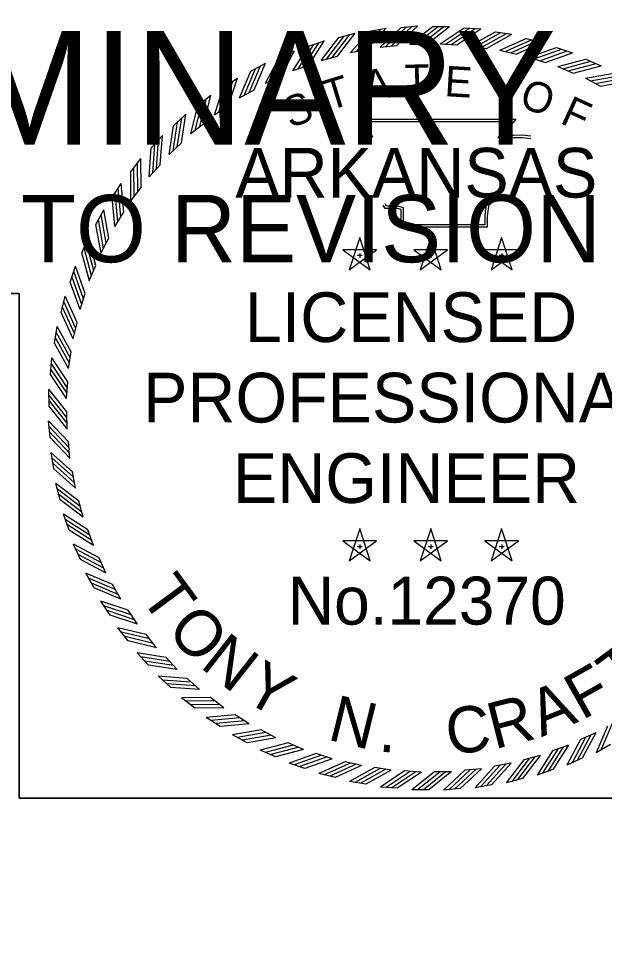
# Model space of a CAD drawing. Extents: x 0 to 1228740, y 0 to 152440.
# Drawn here: x 30.665 to 32.645, y 17.279 to 20.411 of the extents above; entities that cross this region are included whole.
import ezdxf

# ---------------------------------------------------------------- set-up
doc = ezdxf.new("R2010")
doc.units = 0
for name, color, linetype in [('R_Draft', 7, 'Continuous'), ('R_No Plot', 7, 'Continuous'), ('STAMP_TNC', 7, 'Continuous')]:
    doc.layers.add(name, color=color, linetype=linetype)

msp = doc.modelspace()

# ---------------------------------------------------------------- linework, layer by layer
at = {"layer": 'R_No Plot'}
msp.add_lwpolyline([(27.1591, 21.4232), (1.516, 21.4232), (1.516, 10.8708), (33.4231, 10.8708), (33.4231, 17.7768), (30.6665, 17.7768), (30.6665, 19.4815), (28.8871, 19.4815), (28.8871, 20.4352), (27.1591, 20.4352)], close=True, dxfattribs=at)
for points in [[(33.4231, 17.7768), (33.4231, 0.5768), (1.516, 0.5768), (1.516, 21.4232), (27.1591, 21.4232), (27.1591, 20.4352), (28.8871, 20.4352), (28.8871, 19.4815), (30.6665, 19.4815)], [(30.6665, 19.4815), (30.6665, 17.7768), (33.4231, 17.7768)]]:
    msp.add_lwpolyline(points, dxfattribs=at)
at = {"layer": 'STAMP_TNC'}
for p, q in [((31.7473, 20.3469), (31.802, 20.3613)), ((31.8517, 20.3683), (31.9074, 20.3781)), ((31.9576, 20.3809), (32.0139, 20.3861)), ((32.0647, 20.3841), (32.1212, 20.3841)), ((32.1706, 20.3798), (32.227, 20.3757)), ((32.2763, 20.3661), (32.3321, 20.3573)), ((31.645, 20.317), (31.6983, 20.3359)), ((32.0892, 20.3255), (32.1457, 20.3213)), ((32.3805, 20.3437), (32.4354, 20.3303)), ((31.5455, 20.2788), (31.597, 20.302)), ((31.7862, 20.2956), (31.842, 20.3055)), ((31.8862, 20.3139), (31.9427, 20.3191)), ((31.9875, 20.3239), (32.0442, 20.3239)), ((32.1907, 20.3187), (32.2467, 20.3099)), ((32.2913, 20.3035), (32.3464, 20.2901)), ((32.4825, 20.3128), (32.5362, 20.2949)), ((31.688, 20.2691), (31.7428, 20.2835)), ((32.3903, 20.2801), (32.4441, 20.2622)), ((32.5816, 20.2735), (32.6336, 20.2513)), ((31.4495, 20.2325), (31.4989, 20.2598)), ((31.5923, 20.2346), (31.6457, 20.2535)), ((32.487, 20.2485), (32.5391, 20.2262)), ((31.3576, 20.1784), (31.4047, 20.2097)), ((31.4998, 20.1923), (31.5515, 20.2155)), ((32.5808, 20.2091), (32.6309, 20.1826)), ((31.4111, 20.1425), (31.4607, 20.1699)), ((31.2705, 20.1169), (31.3148, 20.152)), ((31.3268, 20.0855), (31.3739, 20.1169)), ((31.1888, 20.0484), (31.2301, 20.0871)), ((31.2475, 20.0218), (31.2919, 20.057)), ((31.1131, 19.9734), (31.151, 20.0154)), ((31.1737, 19.9517), (31.2151, 19.9905)), ((31.0438, 19.8924), (31.0781, 19.9374)), ((31.106, 19.8758), (31.144, 19.9179)), ((30.9814, 19.806), (31.0119, 19.8536)), ((31.0448, 19.7946), (31.0792, 19.8396)), ((30.9264, 19.7147), (30.9528, 19.7647)), ((30.9905, 19.7085), (31.021, 19.7563)), ((30.8791, 19.6192), (30.9013, 19.6712)), ((30.9434, 19.6183), (30.97, 19.6684)), ((31.8175, 19.6706), (31.7822, 19.562)), ((31.8528, 19.5621), (31.8176, 19.6707)), ((32.0574, 19.6706), (32.022, 19.562)), ((32.0927, 19.5621), (32.0575, 19.6707)), ((32.2973, 19.6706), (32.2619, 19.562)), ((32.3325, 19.5621), (32.2973, 19.6707)), ((31.8746, 19.6291), (31.7604, 19.6293)), ((31.7605, 19.6291), (31.8528, 19.562)), ((31.7823, 19.5621), (31.8747, 19.6291)), ((31.8094, 19.6109), (31.8264, 19.6109)), ((31.8176, 19.617), (31.8176, 19.6027)), ((32.1144, 19.6291), (32.0003, 19.6293)), ((32.0004, 19.6291), (32.0927, 19.562)), ((32.0222, 19.5621), (32.1146, 19.6291)), ((32.0493, 19.6109), (32.0662, 19.6109)), ((32.0575, 19.617), (32.0575, 19.6027)), ((32.3543, 19.6291), (32.2401, 19.6293)), ((32.2402, 19.6291), (32.3325, 19.562)), ((32.262, 19.5621), (32.3544, 19.6291)), ((32.2891, 19.6109), (32.3061, 19.6109)), ((32.2974, 19.617), (32.2974, 19.6027)), ((30.8398, 19.5201), (30.8577, 19.5737)), ((30.904, 19.5245), (30.9263, 19.5767)), ((30.8725, 19.4278), (30.8904, 19.4816)), ((30.8089, 19.418), (30.8222, 19.473)), ((30.7865, 19.3138), (30.7952, 19.3697)), ((30.8491, 19.3288), (30.8625, 19.3839)), ((30.7727, 19.2081), (30.7769, 19.2645)), ((30.8339, 19.2282), (30.8427, 19.2842)), ((30.8271, 19.1267), (30.8312, 19.1833)), ((30.7678, 19.1016), (30.7673, 19.1582)), ((30.8287, 19.025), (30.8281, 19.0817)), ((30.7716, 18.9951), (30.7665, 19.0514)), ((30.8386, 18.9238), (30.8334, 18.9802)), ((30.7843, 18.8893), (30.7745, 18.945)), ((30.857, 18.8237), (30.8471, 18.8795)), ((30.8056, 18.7848), (30.7912, 18.8395)), ((30.8835, 18.7255), (30.869, 18.7803)), ((30.8355, 18.6825), (30.8167, 18.7358)), ((30.918, 18.6298), (30.8991, 18.6833)), ((31.8175, 18.6871), (31.7822, 18.5785)), ((31.8528, 18.5786), (31.8176, 18.6872)), ((32.0574, 18.6871), (32.022, 18.5785)), ((32.0927, 18.5786), (32.0575, 18.6872)), ((32.2973, 18.6871), (32.2619, 18.5785)), ((32.3325, 18.5786), (32.2973, 18.6872)), ((30.8738, 18.583), (30.8506, 18.6346)), ((31.8746, 18.6456), (31.7604, 18.6458)), ((31.7605, 18.6456), (31.8528, 18.5785)), ((31.7823, 18.5786), (31.8747, 18.6456)), ((31.8176, 18.6335), (31.8176, 18.6192)), ((32.1144, 18.6456), (32.0003, 18.6458)), ((32.0004, 18.6456), (32.0927, 18.5785)), ((32.0222, 18.5786), (32.1146, 18.6456)), ((32.0575, 18.6335), (32.0575, 18.6192)), ((32.3543, 18.6456), (32.2401, 18.6458)), ((32.2402, 18.6456), (32.3325, 18.5785)), ((32.262, 18.5786), (32.3544, 18.6456)), ((32.2974, 18.6335), (32.2974, 18.6192)), ((31.8094, 18.6274), (31.8264, 18.6274)), ((32.0493, 18.6274), (32.0662, 18.6274)), ((32.2891, 18.6274), (32.3061, 18.6274)), ((30.9603, 18.5373), (30.9371, 18.589)), ((30.9201, 18.487), (30.8927, 18.5365)), ((31.0101, 18.4486), (30.9827, 18.4982)), ((30.9742, 18.3952), (30.9428, 18.4422)), ((31.0671, 18.3643), (31.0356, 18.4115)), ((31.0357, 18.3081), (31.0005, 18.3524)), ((31.1308, 18.285), (31.0956, 18.3294)), ((31.1042, 18.2264), (31.0655, 18.2676)), ((31.2009, 18.2113), (31.1621, 18.2526)), ((31.1792, 18.1506), (31.1372, 18.1885)), ((31.2768, 18.1435), (31.2347, 18.1815)), ((31.2601, 18.0813), (31.2152, 18.1156)), ((31.358, 18.0823), (31.313, 18.1167)), ((31.3466, 18.0189), (31.299, 18.0494)), ((31.444, 18.028), (31.3963, 18.0586)), ((31.5342, 17.981), (31.4841, 18.0075)), ((31.4379, 17.9639), (31.3879, 17.9904)), ((32.6153, 17.9978), (32.5636, 17.9746)), ((31.628, 17.9416), (31.5759, 17.9639)), ((32.5228, 17.9555), (32.4693, 17.9366)), ((32.6656, 17.9576), (32.6161, 17.9303)), ((31.5334, 17.9166), (31.4814, 17.9388)), ((31.7247, 17.9101), (31.671, 17.928)), ((32.4271, 17.921), (32.3722, 17.9066)), ((31.6325, 17.8773), (31.5789, 17.8952)), ((31.8237, 17.8866), (31.7687, 17.9)), ((32.3289, 17.8945), (32.273, 17.8847)), ((32.5696, 17.9113), (32.518, 17.8881)), ((31.7345, 17.8464), (31.6796, 17.8598)), ((31.9243, 17.8714), (31.8683, 17.8803)), ((32.0258, 17.8646), (31.9693, 17.8688)), ((32.1275, 17.8662), (32.0709, 17.8657)), ((32.2288, 17.8762), (32.1723, 17.871)), ((32.4701, 17.8731), (32.4167, 17.8542)), ((31.8387, 17.824), (31.7829, 17.8328)), ((32.2633, 17.8218), (32.2076, 17.812)), ((32.3677, 17.8432), (32.3131, 17.8288)), ((31.9444, 17.8103), (31.8881, 17.8144)), ((32.0509, 17.8053), (31.9944, 17.8048)), ((32.1575, 17.8092), (32.1011, 17.804))]:
    msp.add_line(p, q, dxfattribs=at)
for points in [[(31.7244, 20.2789), (31.7837, 20.3568)], [(31.7427, 20.2836), (31.802, 20.3614)], [(31.7861, 20.2956), (31.8517, 20.3682)], [(31.8041, 20.2986), (31.8696, 20.3712)], [(31.8233, 20.3024), (31.8889, 20.3751)], [(31.8419, 20.3055), (31.9075, 20.3782)], [(31.8862, 20.3139), (31.9575, 20.3809)], [(31.9043, 20.3154), (31.9756, 20.3824)], [(31.9238, 20.3176), (31.9952, 20.3846)], [(31.9426, 20.3192), (32.0139, 20.3862)], [(31.9874, 20.3239), (32.0646, 20.384)], [(32.0056, 20.3237), (32.0828, 20.3839)], [(32.0253, 20.3241), (32.1024, 20.3843)], [(32.0441, 20.3239), (32.1213, 20.3841)], [(32.0891, 20.3254), (32.1705, 20.3798)], [(32.1073, 20.3239), (32.1886, 20.3783)], [(32.1269, 20.3229), (32.2083, 20.3773)], [(32.1457, 20.3214), (32.227, 20.3757)], [(32.1906, 20.3186), (32.2762, 20.3661)], [(32.2086, 20.3156), (32.2942, 20.3631)], [(32.228, 20.313), (32.3136, 20.3605)], [(32.2466, 20.3099), (32.3322, 20.3574)], [(31.6278, 20.2474), (31.6805, 20.3298)], [(31.6456, 20.2535), (31.6983, 20.336)], [(31.6879, 20.269), (31.7472, 20.3469)], [(31.7056, 20.2735), (31.7649, 20.3513)], [(32.2912, 20.3035), (32.3804, 20.3437)], [(32.3089, 20.299), (32.3981, 20.3392)], [(32.328, 20.2948), (32.4172, 20.335)], [(32.3463, 20.2901), (32.4355, 20.3304)], [(31.5341, 20.208), (31.5798, 20.2945)], [(31.5514, 20.2155), (31.5971, 20.3021)], [(31.5922, 20.2345), (31.6449, 20.317)], [(31.6094, 20.2404), (31.6621, 20.3229)], [(32.3902, 20.28), (32.4824, 20.3127)], [(32.4074, 20.2741), (32.4996, 20.3068)], [(32.4262, 20.2683), (32.5184, 20.301)], [(32.444, 20.2622), (32.5362, 20.2949)], [(31.4997, 20.1922), (31.5454, 20.2787)], [(31.5164, 20.1995), (31.5621, 20.286)], [(32.4869, 20.2485), (32.5815, 20.2735)], [(32.5036, 20.2412), (32.5982, 20.2662)], [(31.411, 20.1424), (31.4494, 20.2324)], [(31.427, 20.1511), (31.4654, 20.2411)], [(31.444, 20.1609), (31.4824, 20.2509)], [(31.4606, 20.1699), (31.499, 20.2599)], [(32.5218, 20.2339), (32.6164, 20.2589)], [(32.5391, 20.2263), (32.6337, 20.2513)], [(31.3581, 20.1066), (31.3889, 20.1995)], [(31.3739, 20.1169), (31.4047, 20.2098)], [(32.5807, 20.2091), (32.677, 20.2262)], [(32.5967, 20.2005), (32.6931, 20.2175)], [(32.6143, 20.1916), (32.7106, 20.2087)], [(32.6308, 20.1827), (32.7272, 20.1998)], [(31.3267, 20.0854), (31.3576, 20.1783)], [(31.342, 20.0954), (31.3728, 20.1882)], [(31.2769, 20.0454), (31.3, 20.1405)], [(31.2918, 20.057), (31.3149, 20.1521)], [(31.2475, 20.0217), (31.2705, 20.1168)], [(31.2618, 20.0329), (31.2849, 20.128)], [(31.2011, 19.9777), (31.2162, 20.0744)], [(31.215, 19.9905), (31.2301, 20.0871)], [(31.1737, 19.9516), (31.1888, 20.0483)], [(31.1871, 19.964), (31.2022, 20.0606)], [(31.854, 20.0056), (31.8238, 20.0709), (32.3454, 20.0712), (32.3018, 20.0164), (32.3372, 20.0169), (32.3668, 20.0173), (32.3964, 20.0141)], [(31.8615, 20.0091), (31.8367, 20.0626), (32.3282, 20.0629), (32.2845, 20.0079), (32.3373, 20.0086), (32.3664, 20.009), (32.3955, 20.0058)], [(31.1439, 19.9178), (31.151, 20.0154)], [(31.1183, 19.8891), (31.1254, 19.9867)], [(31.1312, 19.904), (31.1382, 20.0016)], [(31.106, 19.8757), (31.1131, 19.9733)], [(31.0675, 19.8247), (31.0665, 19.9226)], [(31.0791, 19.8396), (31.0781, 19.9374)], [(31.0448, 19.7945), (31.0438, 19.8923)], [(31.0559, 19.8088), (31.0549, 19.9067)], [(31.0106, 19.7405), (31.0016, 19.8379)], [(31.021, 19.7562), (31.0119, 19.8537)], [(30.9905, 19.7085), (30.9814, 19.8059)], [(31.0004, 19.7237), (30.9913, 19.8211)], [(32.258, 19.7934), (32.247, 19.7845), (32.2432, 19.7705), (32.2401, 19.7424), (32.2401, 19.7142), (31.9655, 19.7142), (31.9655, 19.7546), (31.9655, 19.7715), (31.9467, 19.7772), (31.9085, 19.7772), (31.9036, 19.7847)], [(30.9699, 19.6684), (30.9528, 19.7647)], [(32.2632, 19.787), (32.2543, 19.7798), (32.2513, 19.769), (32.2484, 19.742), (32.2484, 19.7059), (31.9572, 19.7059), (31.9572, 19.7546), (31.9572, 19.7654), (31.9454, 19.769), (31.904, 19.769), (31.8967, 19.7802)], [(30.9521, 19.6343), (30.935, 19.7306)], [(30.9609, 19.6518), (30.9438, 19.7482)], [(30.9435, 19.6183), (30.9264, 19.7146)], [(30.9263, 19.5766), (30.9013, 19.6712)], [(30.9114, 19.5411), (30.8864, 19.6357)], [(30.9187, 19.5594), (30.8937, 19.654)], [(30.9041, 19.5245), (30.8791, 19.6191)], [(30.8904, 19.4816), (30.8576, 19.5738)], [(30.8842, 19.4637), (30.8515, 19.556)], [(30.8725, 19.4277), (30.8398, 19.52)], [(30.8784, 19.445), (30.8457, 19.5372)], [(30.8578, 19.3656), (30.8176, 19.4548)], [(30.8624, 19.3839), (30.8222, 19.4731)], [(30.8491, 19.3288), (30.8089, 19.418)], [(30.8536, 19.3464), (30.8134, 19.4356)], [(30.8427, 19.2842), (30.7952, 19.3698)], [(30.8369, 19.2461), (30.7895, 19.3317)], [(30.8396, 19.2656), (30.7921, 19.3512)], [(30.8339, 19.2282), (30.7865, 19.3137)], [(30.8312, 19.1832), (30.7768, 19.2646)], [(30.8296, 19.1644), (30.7753, 19.2458)], [(30.8271, 19.1267), (30.7728, 19.208)], [(30.8286, 19.1448), (30.7743, 19.2262)], [(30.8281, 19.0816), (30.7672, 19.1582)], [(30.8281, 19.0628), (30.7672, 19.1394)], [(30.8287, 19.0432), (30.7678, 19.1198)], [(30.8287, 19.025), (30.7678, 19.1016)], [(30.8334, 18.9802), (30.7664, 19.0515)], [(30.835, 18.9614), (30.768, 19.0327)], [(30.8372, 18.9419), (30.7702, 19.0132)], [(30.8387, 18.9237), (30.7717, 18.995)], [(30.8471, 18.8795), (30.7744, 18.945)], [(30.8502, 18.8609), (30.7775, 18.9264)], [(30.854, 18.8416), (30.7814, 18.9072)], [(30.857, 18.8237), (30.7844, 18.8892)], [(30.869, 18.7802), (30.7912, 18.8396)], [(30.8736, 18.762), (30.7958, 18.8213)], [(30.8791, 18.7431), (30.8012, 18.8024)], [(30.8835, 18.7255), (30.8057, 18.7848)], [(30.8991, 18.6832), (30.8166, 18.7359)], [(30.9052, 18.6654), (30.8227, 18.718)], [(30.9121, 18.647), (30.8297, 18.6997)], [(30.9181, 18.6298), (30.8356, 18.6825)], [(30.937, 18.5889), (30.8505, 18.6346)], [(30.9446, 18.5717), (30.8581, 18.6174)], [(30.9531, 18.5539), (30.8665, 18.5996)], [(30.9604, 18.5373), (30.8738, 18.583)], [(30.9827, 18.4981), (30.8927, 18.5365)], [(30.9916, 18.4816), (30.9016, 18.5199)], [(31.0015, 18.4646), (30.9115, 18.503)], [(31.0102, 18.4486), (30.9202, 18.487)], [(31.0356, 18.4114), (30.9428, 18.4422)], [(31.0459, 18.3956), (30.9531, 18.4265)], [(31.0572, 18.3795), (30.9643, 18.4104)], [(31.0671, 18.3643), (30.9743, 18.3951)], [(31.0956, 18.3294), (31.0005, 18.3524)], [(31.1071, 18.3145), (31.0121, 18.3375)], [(31.1197, 18.2994), (31.0246, 18.3224)], [(31.1309, 18.285), (31.0358, 18.3081)], [(31.1621, 18.2525), (31.0654, 18.2677)], [(31.1749, 18.2387), (31.0782, 18.2538)], [(31.1886, 18.2246), (31.0919, 18.2398)], [(31.2009, 18.2112), (31.1043, 18.2264)], [(31.2347, 18.1815), (31.1371, 18.1886)], [(31.2486, 18.1687), (31.151, 18.1758)], [(31.2635, 18.1559), (31.1659, 18.1629)], [(31.2768, 18.1435), (31.1793, 18.1506)], [(31.313, 18.1166), (31.2151, 18.1156)], [(31.3279, 18.1051), (31.23, 18.1041)], [(31.3437, 18.0935), (31.2459, 18.0925)], [(31.3581, 18.0823), (31.2602, 18.0813)], [(31.3963, 18.0585), (31.2989, 18.0494)], [(31.4121, 18.0482), (31.3147, 18.0391)], [(31.4289, 18.038), (31.3314, 18.0289)], [(31.4441, 18.028), (31.3467, 18.0189)], [(31.4842, 18.0074), (31.3878, 17.9904)], [(32.6544, 18.0202), (32.6161, 17.9302)], [(32.671, 18.0292), (32.6326, 17.9392)], [(31.5007, 17.9985), (31.4044, 17.9814)], [(31.5183, 17.9897), (31.422, 17.9726)], [(31.5343, 17.981), (31.438, 17.9639)], [(32.5809, 17.9822), (32.5352, 17.8956)], [(32.5986, 17.9906), (32.5529, 17.9041)], [(32.6153, 17.9979), (32.5696, 17.9114)], [(31.576, 17.9638), (31.4813, 17.9388)], [(31.5932, 17.9562), (31.4986, 17.9313)], [(31.6114, 17.9489), (31.5168, 17.9239)], [(32.5056, 17.9497), (32.4529, 17.8672)], [(32.5228, 17.9556), (32.4701, 17.8731)], [(32.5636, 17.9746), (32.518, 17.8881)], [(31.6281, 17.9416), (31.5335, 17.9166)], [(31.671, 17.9279), (31.5788, 17.8952)], [(31.6888, 17.9218), (31.5966, 17.8891)], [(31.7076, 17.916), (31.6154, 17.8833)], [(32.4095, 17.9166), (32.3502, 17.8388)], [(32.4271, 17.9211), (32.3678, 17.8433)], [(32.4694, 17.9366), (32.4167, 17.8542)], [(32.4872, 17.9427), (32.4345, 17.8603)], [(31.7248, 17.9101), (31.6326, 17.8774)], [(31.7687, 17.9), (31.6795, 17.8598)], [(31.787, 17.8954), (31.6978, 17.8551)], [(31.8062, 17.8911), (31.717, 17.8509)], [(31.8238, 17.8867), (31.7346, 17.8464)], [(32.2731, 17.8846), (32.2076, 17.812)], [(32.2917, 17.8877), (32.2262, 17.8151)], [(32.311, 17.8916), (32.2454, 17.8189)], [(32.3289, 17.8946), (32.2634, 17.8219)], [(32.3723, 17.9066), (32.313, 17.8287)], [(32.3906, 17.9112), (32.3313, 17.8334)], [(31.8684, 17.8802), (31.7828, 17.8328)], [(31.887, 17.8771), (31.8014, 17.8297)], [(31.9064, 17.8745), (31.8209, 17.827)], [(31.9244, 17.8715), (31.8388, 17.824)], [(31.9694, 17.8687), (31.888, 17.8144)], [(31.9881, 17.8672), (31.9068, 17.8128)], [(32.0078, 17.8662), (31.9264, 17.8118)], [(32.0259, 17.8647), (31.9445, 17.8103)], [(32.0709, 17.8657), (31.9943, 17.8048)], [(32.0898, 17.8657), (32.0132, 17.8048)], [(32.1094, 17.8663), (32.0328, 17.8054)], [(32.1276, 17.8663), (32.051, 17.8054)], [(32.1724, 17.871), (32.1011, 17.804)], [(32.1912, 17.8725), (32.1199, 17.8055)], [(32.2107, 17.8747), (32.1394, 17.8077)], [(32.2288, 17.8763), (32.1575, 17.8093)]]:
    msp.add_lwpolyline(points, dxfattribs=at)

# ---------------------------------------------------------------- texts
at = {"layer": 'R_Draft'}
for s, height, p in [('PRELIMINARY', 0.383593, (29.0049, 19.9851)), ('SUBJECT TO REVISION', 0.227428, (29.2031, 19.5873))]:
    msp.add_text(s, height=height, rotation=0, dxfattribs=at).set_placement(p)
at = {"layer": 'STAMP_TNC'}
for s, height, rotation, p in [('A', 0.1029, 8.6788, (31.8381, 20.1312)), ('T', 0.1029, 1.4789, (31.9709, 20.1516)), ('E', 0.1029, 356.672, (32.1026, 20.1485)), ('T', 0.1029, 16.9015, (31.7131, 20.0985)), ('O', 0.1029, 341.2218, (32.3524, 20.1132)), ('S', 0.1029, 19.7726, (31.5823, 20.0398)), ('F', 0.1029, 335.3628, (32.491, 20.059)), ('T', 0.1562, 306.5026, (31.0716, 18.4581)), ('O', 0.1562, 313.7811, (31.1603, 18.3383)), ('N', 0.1562, 321.7876, (31.2744, 18.2207)), ('T', 0.1562, 36.7567, (32.6989, 18.112)), ('Y', 0.1562, 330.5218, (31.4163, 18.1119)), ('F', 0.1562, 29.4782, (32.5692, 18.0387)), ('A', 0.1562, 22.1996, (32.4312, 17.9824)), ('N', 0.1562, 346.1707, (31.7053, 17.9754)), ('R', 0.1562, 14.1932, (32.2726, 17.9412)), ('C', 0.1562, 6.5507, (32.1172, 17.9228)), ('.', 0.1562, 354.905, (31.8794, 17.9349))]:
    msp.add_text(s, height=height, rotation=rotation, dxfattribs=at).set_placement(p)
for s, height, p in [('ARKANSAS', 0.16791, (31.3975, 19.8058)), ('LICENSED', 0.16791, (31.4295, 19.3178)), ('PROFESSIONAL', 0.167907, (31.0857, 19.0459)), ('ENGINEER', 0.16791, (31.3895, 18.7741)), ('No.12370', 0.16191, (31.5747, 18.3631))]:
    msp.add_text(s, height=height, dxfattribs=at).set_placement(p)

doc.saveas('drawing.dxf')
